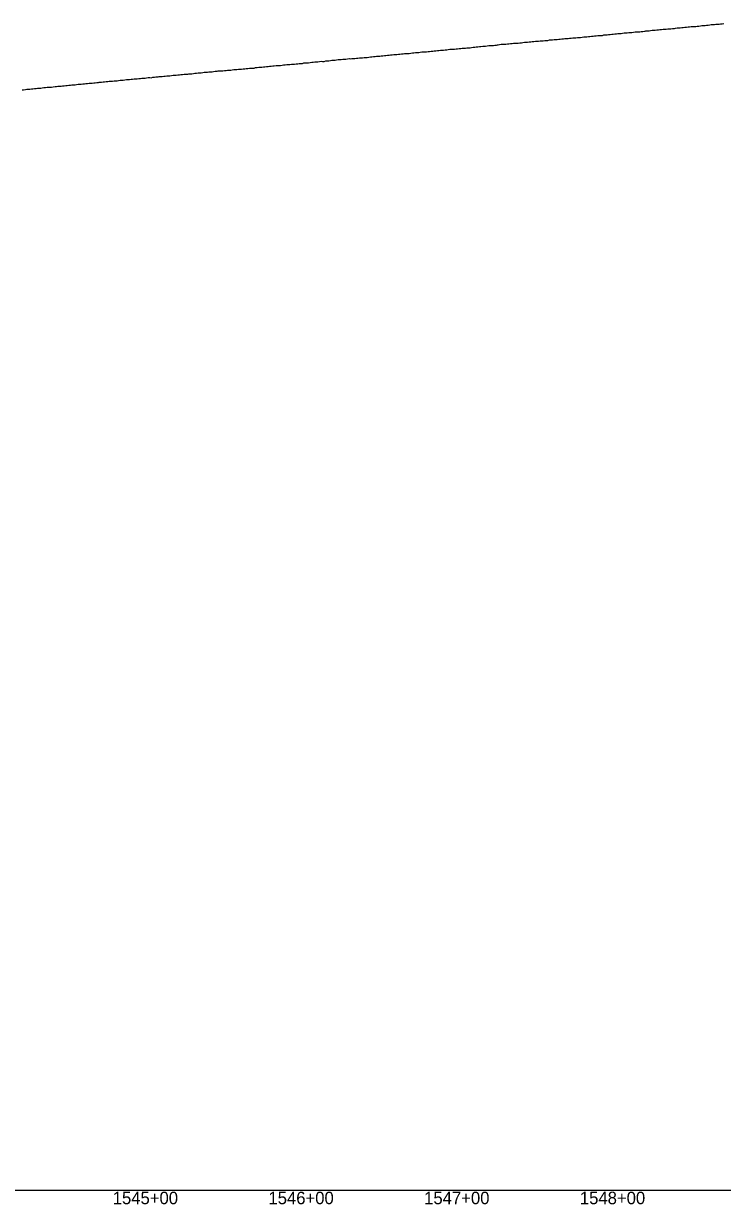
# Model space of a CAD drawing. Extents: x -3793 to 50787, y -1075 to 6138.
# Drawn here: x 41862 to 42310, y -1009 to -251 of the extents above; entities that cross this region are included whole.
import ezdxf

# ---------------------------------------------------------------- set-up
doc = ezdxf.new("R2010")
doc.units = 0
for name, color, linetype in [('RD_DDB_Profile_EX', 7, 'Continuous'), ('RD_DDB_StaTX', 7, 'Continuous'), ('RD_GPK_Profile_Cell', 7, 'Continuous')]:
    doc.layers.add(name, color=color, linetype=linetype)

msp = doc.modelspace()

# ---------------------------------------------------------------- linework, layer by layer
at = {"layer": 'RD_DDB_Profile_EX'}
for points in [[(42153.430417, -265.79088), (42154.430411, -265.741415), (42155.430404, -265.591615), (42156.619255, -265.512945), (42157.430577, -265.392455), (42158.43075, -265.342095), (42159.430714, -265.193025), (42160.430677, -265.09391), (42161.430851, -265.04294), (42162.430815, -265.042655), (42163.430988, -264.941625), (42164.430951, -264.693215), (42165.430915, -264.69387), (42166.091058, -264.594605), (42166.431079, -264.54405), (42167.431013, -264.445215), (42168.431108, -264.194955), (42169.431048, -264.244915), (42170.431191, -264.24439), (42171.431132, -264.095335), (42172.431072, -263.94605), (42173.431215, -263.84594), (42174.431155, -263.74678), (42175.562862, -263.683275), (42176.431214, -263.5971), (42177.431128, -263.49777), (42178.431243, -263.397555), (42179.421167, -263.3983), (42180.421284, -263.34808), (42181.42119, -263.19896), (42182.421096, -263.049775), (42183.421213, -262.89959), (42183.982172, -262.87195), (42184.421272, -262.85033), (42185.034666, -262.81954), (42185.421301, -262.800155), (42186.421566, -262.65103), (42187.4216, -262.600905), (42188.421635, -262.50075), (42189.421899, -262.401575), (42190.421933, -262.301455), (42191.421968, -262.201395), (42192.421992, -262.15122), (42193.422248, -262.051955), (42194.50647, -261.94762), (42195.422328, -261.901715), (42196.422373, -261.8016), (42197.422419, -261.75149), (42198.422685, -261.70235), (42199.42273, -261.452665), (42200.422775, -261.402395), (42201.412844, -261.30248), (42202.413118, -261.15365), (42203.413163, -261.10361), (42203.978274, -261.075335), (42204.413213, -261.053455), (42205.413268, -261.00319), (42206.413553, -260.95389), (42207.413608, -260.754515), (42208.413665, -260.70436), (42209.41372, -260.604195), (42210.414005, -260.455335), (42211.41406, -260.40537), (42212.414116, -260.35541), (42213.450078, -260.25214), (42214.414468, -260.157045), (42215.414535, -260.105975), (42216.414602, -260.006385), (42217.414669, -259.95649), (42218.414964, -259.85781), (42219.415033, -259.75757), (42220.4151, -259.70731), (42221.415167, -259.507785), (42222.415234, -259.457895), (42222.921882, -259.458385), (42223.415535, -259.458045), (42224.415614, -259.259505), (42225.415468, -259.208405), (42226.415548, -259.10859), (42227.405476, -259.0083), (42228.405557, -258.858875), (42229.405331, -258.758135), (42230.405413, -258.659065), (42231.405262, -258.55759), (42232.405342, -258.556775), (42233.405433, -258.50666), (42234.405295, -258.20772), (42235.405388, -258.157675), (42236.40525, -258.057005), (42237.405341, -257.95728), (42238.405205, -257.856615), (42239.405297, -257.80689), (42240.405159, -257.75595), (42241.405252, -257.606215), (42241.86549, -257.53731), (42242.40535, -257.45711), (42243.405227, -257.3565), (42244.405332, -257.256865), (42245.405209, -257.205995), (42246.405314, -257.05635), (42247.405191, -256.95576)], [(42247.405191, -256.95576), (42248.405297, -256.856385), (42249.405402, -256.805905), (42250.405278, -256.705625), (42251.405385, -256.6557), (42252.405277, -256.60499), (42253.405396, -256.50536), (42254.405288, -256.305665), (42255.405407, -256.256095), (42256.405298, -256.2551), (42257.405419, -256.1555), (42258.405538, -256.00617), (42259.405429, -255.905685), (42260.405548, -255.856095), (42260.809098, -255.755005), (42261.405449, -255.606435), (42262.405583, -255.60615), (42263.40549, -255.55548), (42264.405625, -255.406515), (42265.405531, -255.25635), (42266.405665, -255.206305), (42267.395801, -255.1068), (42268.395708, -254.9561), (42269.395841, -254.85594), (42270.395751, -254.8056), (42271.3959, -254.70672), (42272.395822, -254.607015), (42273.395745, -254.506375), (42274.395668, -254.40605), (42275.39559, -254.355195), (42276.395513, -254.25514), (42277.395208, -254.20397), (42278.39513, -254.053825), (42279.395052, -254.05302), (42279.752706, -254.017145), (42280.394985, -253.95263), (42281.394924, -253.70309), (42282.394862, -253.702695), (42283.394572, -253.55154), (42284.394511, -253.501225), (42285.394449, -253.35107), (42286.394387, -253.30073), (42287.394326, -253.300415), (42288.607653, -253.05), (42289.394414, -253.04913), (42290.394459, -252.849055), (42291.394503, -252.748835), (42292.394548, -252.748455), (42293.394593, -252.69826), (42294.394847, -252.59737), (42295.394891, -252.497335), (42296.394936, -252.347165), (42297.39498, -252.196995), (42298.395025, -252.14666), (42298.696314, -252.131545), (42299.395056, -252.09636), (42300.395291, -251.99556), (42301.395316, -251.89546), (42302.385388, -251.795585), (42303.385414, -251.59573), (42304.38544, -251.545395), (42305.385467, -251.49505), (42306.38571, -251.39408), (42307.385677, -251.343975), (42308.385698, -251.243885), (42309.385706, -251.144165), (42310.385713, -251.044135), (42311.385721, -250.944105)], [(42055.735584, -274.884755), (42056.73593, -274.835965), (42057.735999, -274.739375), (42058.736349, -274.53557), (42059.736415, -274.48688), (42060.736765, -274.38733), (42061.901215, -274.3132), (42062.737144, -274.19044), (42063.737452, -274.08684), (42064.737474, -274.037505), (42065.737781, -273.93732), (42066.737807, -273.83734), (42067.738111, -273.786515), (42068.738137, -273.687235), (42069.738444, -273.637035), (42070.724386, -273.440695), (42071.457835, -273.587215), (42072.458091, -273.43771), (42073.458346, -273.43697), (42074.458602, -273.336845), (42075.458728, -273.187365), (42076.458983, -273.087885), (42077.459237, -272.987775), (42078.459694, -272.935445), (42079.459948, -272.88462), (42080.450337, -272.735215), (42080.844823, -272.715445), (42081.450568, -272.68515), (42082.450788, -272.6344), (42083.451008, -272.58435), (42084.451228, -272.28573), (42085.451449, -272.23354), (42086.451669, -272.084925), (42087.451889, -272.03488), (42088.452106, -271.93557), (42089.452326, -271.834805), (42090.452542, -271.78477), (42091.452727, -271.635525), (42092.452913, -271.534835), (42093.453308, -271.43548), (42094.45349, -271.334), (42095.453675, -271.18479), (42096.453709, -271.183305), (42097.453895, -271.034855), (42098.454081, -270.886395), (42099.454266, -270.83567), (42099.788431, -270.818975), (42100.454427, -270.78726), (42101.444723, -270.738105), (42102.444874, -270.6345), (42103.445026, -270.58388), (42104.445177, -270.43472), (42105.445329, -270.334835), (42106.44548, -270.23566), (42107.445629, -270.08578), (42108.445989, -270.084265), (42109.446135, -270.033645), (42110.446253, -269.836045), (42111.446372, -269.736215), (42112.44649, -269.684955), (42113.446605, -269.585865), (42114.446724, -269.48674), (42115.446842, -269.435535), (42116.447024, -269.28553), (42117.447145, -269.136425), (42118.732039, -269.08594), (42119.447362, -269.08404), (42120.447448, -269.035025), (42121.447537, -268.935305), (42122.447825, -268.784625), (42123.447914, -268.73353), (42124.448005, -268.733145), (42125.448093, -268.43611), (42126.448182, -268.385725), (42127.438396, -268.284735), (42128.438474, -268.185685), (42129.438737, -268.08636), (42130.438794, -267.98542), (42131.438848, -267.886415), (42132.438902, -267.787375), (42133.438959, -267.68654), (42134.439013, -267.586915), (42135.439067, -267.437845), (42136.439333, -267.387235), (42137.675647, -267.374745), (42138.439418, -267.33638), (42139.439443, -267.236345), (42140.439365, -267.037375), (42141.439392, -266.938845), (42142.439622, -266.83829), (42143.439649, -266.788265), (42144.439676, -266.738745), (42145.439705, -266.68832), (42146.439732, -266.538845), (42147.43975, -266.4398), (42148.43995, -266.388865), (42149.439948, -266.239485), (42150.439945, -266.140865), (42151.430222, -266.08999), (42152.430214, -265.89134), (42153.430417, -265.79088)], [(41958.748283, -284.088485), (41959.748815, -284.037085), (41960.749348, -283.93696), (41961.749601, -283.88894), (41962.750133, -283.69069), (41963.750385, -283.589505), (41964.750918, -283.48939), (41965.75145, -283.389875), (41966.751702, -283.3394), (41967.183175, -283.317785), (41967.752206, -283.289325), (41968.752408, -283.14011), (41969.742982, -283.090085), (41970.743465, -282.940565), (41971.743658, -282.79131), (41972.744044, -282.74078), (41973.744527, -282.640245), (41974.744728, -282.59063), (41975.74521, -282.441475), (41976.745406, -282.34268), (41977.74584, -282.193515), (41978.746273, -282.093535), (41979.746424, -282.0439), (41980.746858, -281.943925), (41981.747008, -281.894695), (41982.73749, -281.84474), (41983.737924, -281.64476), (41984.738064, -281.5458), (41985.738497, -281.495295), (41986.126783, -281.43738), (41986.738607, -281.346375), (41987.738949, -281.29646), (41988.739619, -281.24554), (41989.740004, -281.195385), (41990.740672, -281.045205), (41991.741057, -280.945565), (41992.741726, -280.89462), (41993.742111, -280.845015), (41994.742779, -280.74404), (41995.743157, -280.644135), (41996.743777, -280.49315), (41997.744396, -280.4421), (41998.744733, -280.34267), (41999.745352, -280.192035), (42000.74569, -280.14176), (42001.746215, -280.14109), (42002.736634, -279.942655), (42003.737252, -279.94061), (42004.737593, -279.79125), (42005.070391, -279.75778), (42005.738182, -279.690655), (42006.738754, -279.63954), (42007.739047, -279.58869), (42008.739621, -279.537445), (42009.739912, -279.48772), (42010.740486, -279.18938), (42011.74078, -279.139015), (42012.74135, -278.989635), (42013.741925, -278.889095), (42014.742206, -278.837435), (42015.742734, -278.73687), (42016.742981, -278.58782), (42017.743506, -278.487295), (42018.743753, -278.43759), (42019.744282, -278.2891), (42020.744526, -278.237365), (42021.745054, -278.088215), (42022.745582, -278.088455), (42024.013999, -277.860365), (42024.74632, -277.786845), (42025.73665, -277.7858), (42026.737138, -277.73458), (42027.737193, -277.63641), (42028.737672, -277.48596), (42029.737874, -277.386325), (42030.738357, -277.286605), (42031.738835, -277.186175), (42032.739037, -277.134275), (42033.739509, -276.986095), (42034.739662, -276.98577), (42035.7401, -276.93307), (42036.740257, -276.78432), (42037.740691, -276.68543), (42038.741128, -276.535035), (42039.741282, -276.48472), (42040.741719, -276.48352), (42041.741877, -276.18705), (42042.957607, -276.222925), (42043.742433, -276.183365), (42044.742827, -276.033765), (42045.742936, -275.83583), (42046.74333, -275.734745), (42047.733869, -275.6852), (42048.733973, -275.586475), (42049.73437, -275.53463), (42050.734473, -275.435175), (42051.73487, -275.23559), (42052.734965, -275.13685), (42053.735164, -275.282165), (42054.735234, -275.232185), (42055.735584, -274.884755)], [(41862.993332, -293.327895), (41863.766852, -293.1366), (41864.76779, -293.134335), (41865.768576, -292.985035), (41866.759479, -292.88645), (41867.760264, -292.787145), (41868.76105, -292.63716), (41869.762124, -292.58491), (41870.76291, -292.48493), (41871.763696, -292.38495), (41872.764468, -292.28569), (41873.765196, -292.186495), (41874.766213, -291.987255), (41875.766792, -291.936585), (41876.76752, -291.83519), (41877.768249, -291.78528), (41878.759106, -291.73541), (41879.760122, -291.68463), (41880.76085, -291.58472), (41881.93694, -291.331375), (41882.762259, -291.28647), (41883.762935, -291.18661), (41884.763894, -291.135975), (41885.764411, -291.036895), (41886.765083, -290.98551), (41887.765756, -290.884915), (41888.766433, -290.685815), (41889.757524, -290.585175), (41890.758195, -290.535335), (41891.408744, -290.470425), (41891.758846, -290.43552), (41892.759465, -290.335735), (41893.76008, -290.285965), (41894.760983, -290.186905), (41895.761598, -290.03635), (41896.762213, -289.88806), (41897.762685, -289.835305), (41898.763302, -289.735545), (41899.764199, -289.68416), (41900.880548, -289.561825), (41901.755518, -289.386935), (41902.756077, -289.33651), (41903.756636, -289.236115), (41904.757484, -289.087), (41905.758043, -289.08587), (41906.758607, -289.035485), (41907.759166, -288.98514), (41908.759593, -288.738125), (41909.760436, -288.686935), (41910.352352, -288.627955), (41910.76098, -288.587255), (41911.761768, -288.488185), (41912.762277, -288.38919), (41913.753188, -288.33604), (41914.753985, -288.18699), (41915.75449, -288.03945), (41916.755283, -287.989085), (41917.755787, -287.93584), (41918.75658, -287.884625), (41919.824156, -287.77897), (41920.757684, -287.686055), (41921.758418, -287.58416), (41922.758874, -287.533915), (41923.759612, -287.33571), (41924.760346, -287.236095), (41925.760802, -287.185015), (41926.761536, -287.036915), (41927.752411, -286.933445), (41928.752867, -286.883915), (41929.29596, -286.883675), (41929.75358, -286.881955), (41930.753979, -286.635605), (41931.754508, -286.63374), (41932.755193, -286.48496), (41933.755597, -286.434705), (41934.756278, -286.384375), (41935.756682, -286.235665), (41936.757363, -286.08535), (41937.758048, -286.035025), (41938.767764, -285.984585), (41939.75909, -285.884485), (41940.759446, -285.735825), (41941.750217, -285.635595), (41942.750853, -285.633025), (41943.751204, -285.731455), (41944.751689, -285.38489), (41945.752044, -285.286215), (41946.752678, -285.186695), (41947.753312, -285.134945), (41948.239568, -285.06233), (41948.753637, -284.985595), (41949.75422, -284.88613), (41950.754803, -284.8352), (41951.755107, -284.73658), (41952.75569, -284.63639), (41953.755994, -284.48703), (41954.756577, -284.388225), (41955.747285, -284.38598), (41956.747583, -284.23799), (41957.748166, -284.13849), (41958.748283, -284.088485)], [(41860.764365, -293.486085), (41861.765209, -293.534115), (41862.993332, -293.327895)]]:
    msp.add_lwpolyline(points, dxfattribs=at)
at = {"layer": 'RD_GPK_Profile_Cell'}
msp.add_line((1000, -1000), (46610.921919, -1000), dxfattribs=at)

# ---------------------------------------------------------------- texts
at = {"layer": 'RD_DDB_StaTX'}
for s, p in [('1545+00', (41918.971301, -1009)), ('1546+00', (42018.971301, -1009)), ('1547+00', (42118.971301, -1009)), ('1548+00', (42218.971301, -1009))]:
    msp.add_text(s, height=8, dxfattribs=at).set_placement(p)

doc.saveas('drawing.dxf')
